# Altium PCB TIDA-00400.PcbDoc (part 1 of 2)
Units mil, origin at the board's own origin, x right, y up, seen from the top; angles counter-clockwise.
Board outline 2000 x 2000 mil, 2 copper layers (Top Layer, Bottom Layer), stack 62 mil thick; 123 components, 39 nets, 250 pads, 73 vias.
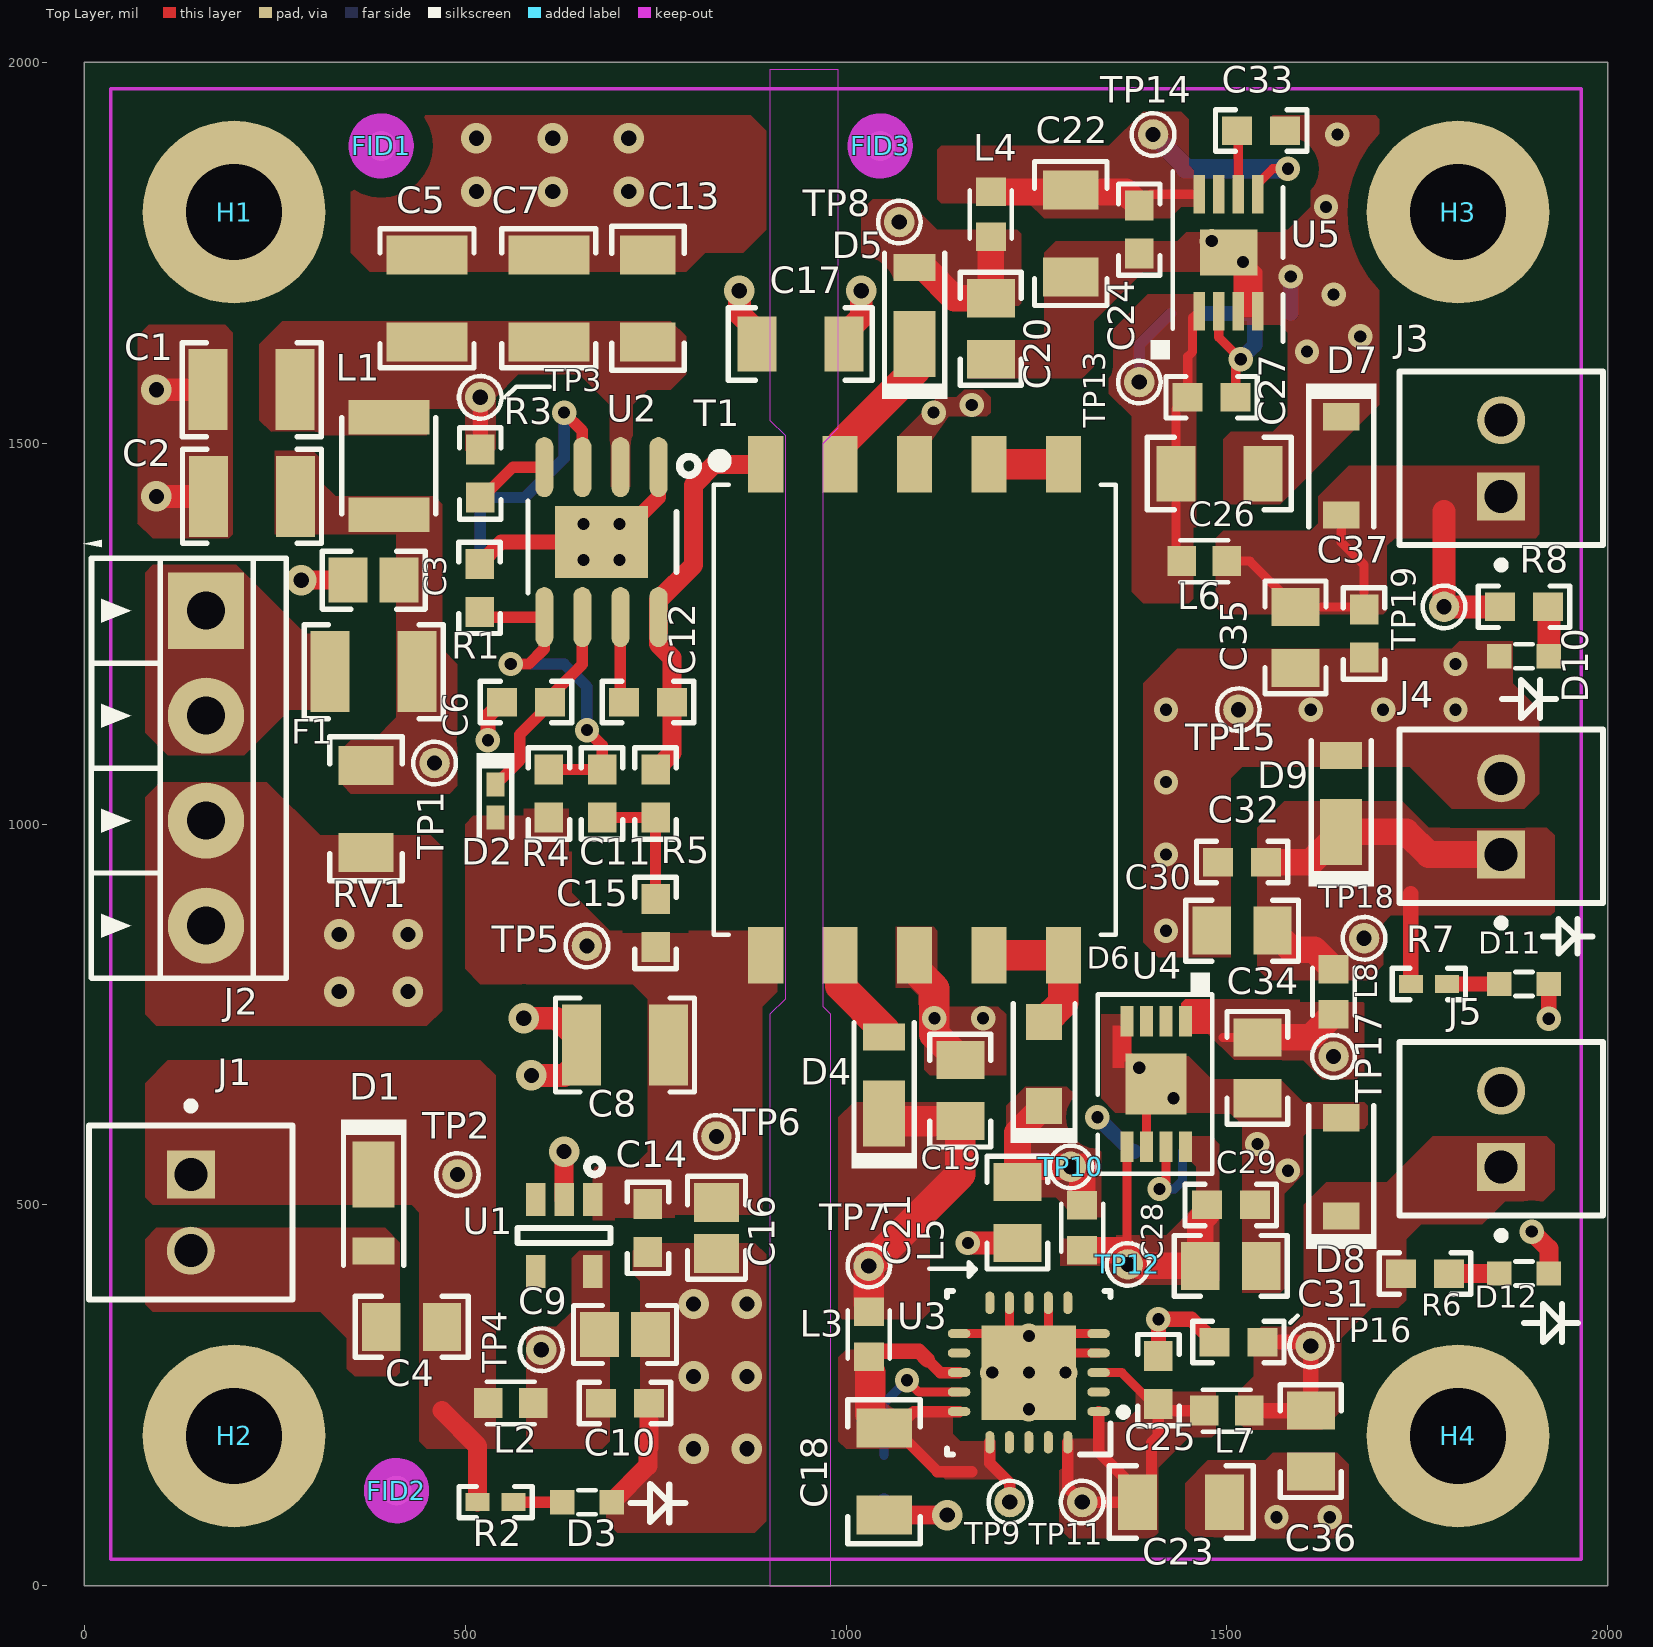
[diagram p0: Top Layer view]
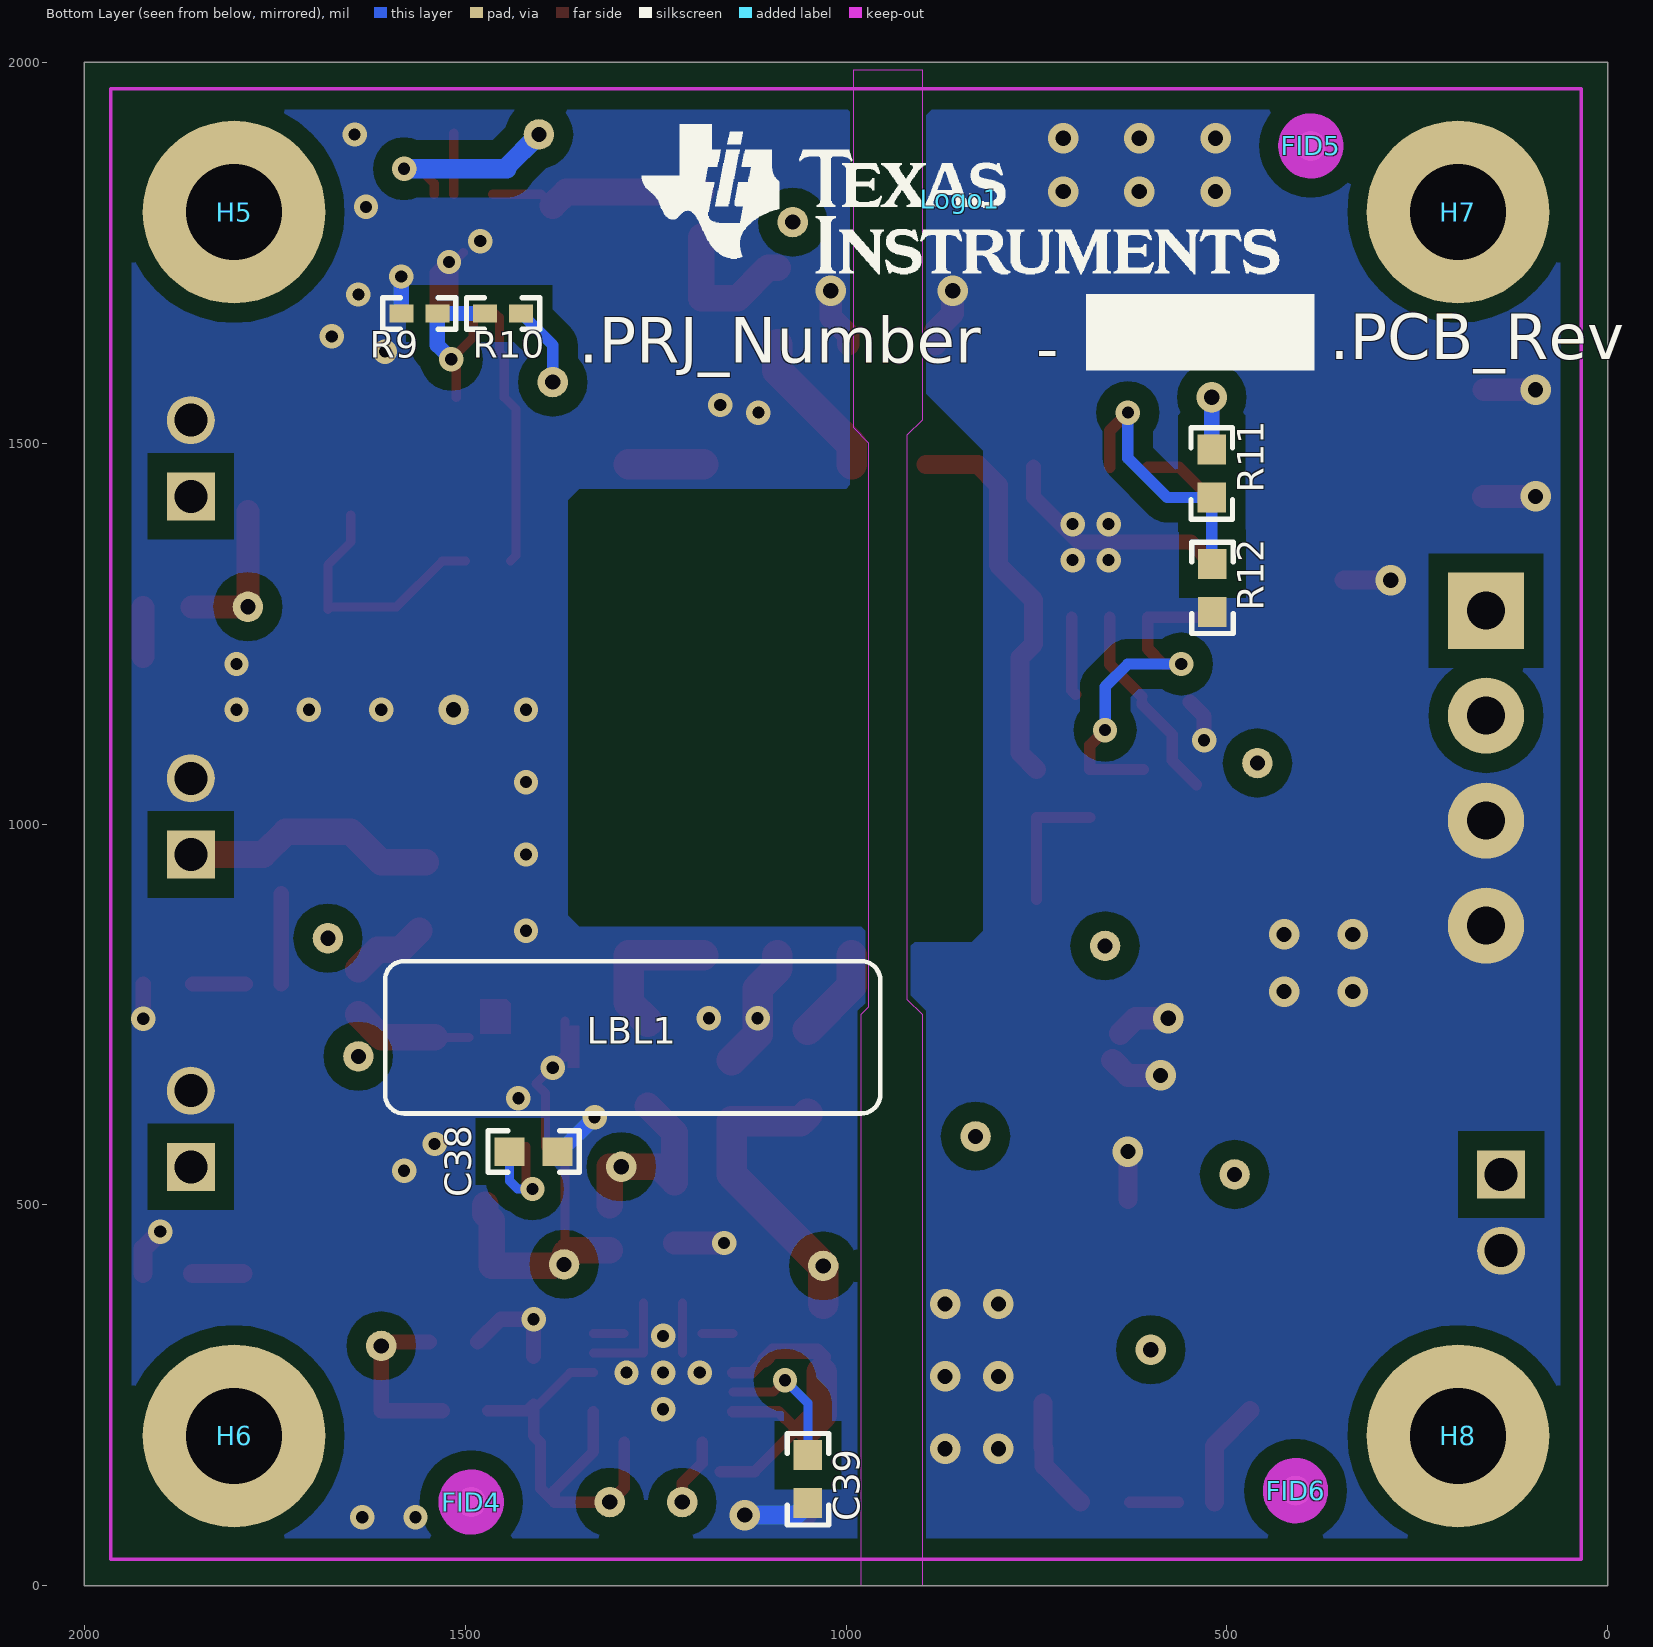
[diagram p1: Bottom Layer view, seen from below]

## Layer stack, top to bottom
Top Layer: signal copper 1.4
Dielectric: core 59.2, FR-4, Dk 4.8
Bottom Layer: signal copper 1.4

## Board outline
0,0 0,2000 2000,2000 2000,0

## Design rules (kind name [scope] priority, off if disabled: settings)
AcuteAngle [All] p1: minimum=4.50000000000000E+0001 checktracksonly=FALSE
AssemblyTestPointUsage [All] p1: valid=2
Clearance "Pad to Pad" [(InPadClass('Pad Class')) vs (InPadClass('Pad Class'))] p1: gap=8.6
Clearance "via 2 SMD Pin" [IsSMTPin vs IsVia] p2: gap=12
Clearance "Via 2 Via" [IsVia vs IsVia] p3: gap=10
Clearance Clearance_BoardEdge_MountingHoles [OnCopper and InComponentClass('Mounting Holes') vs IsKeepOut] p4: gap=40
Clearance Clearance_BoardEdge_Poly [OnCopper and InPoly vs IsKeepOut] p5: gap=25
Clearance Clearance_Poly [InPolygon] p6: gap=25
Clearance [All] p7: gap=11
ComponentClearance ComponentClearance_Shunt [InComponentClass('Header') vs InComponentClass('Shunt')] p1: gap=0 collisioncheckmode=3 verticalgap=0 showdistances=FALSE
ComponentClearance ComponentClearance_Logo [InComponentClass('Logo')] p2: gap=50 collisioncheckmode=3 verticalgap=10 showdistances=FALSE
ComponentClearance ComponentClearance_ScrewToNut [(HasFootprint('NY PMS 440 0025 PH')) vs (HasFootprint('Keystone_1902C'))] p3: gap=5 collisioncheckmode=3 verticalgap=10 showdistances=FALSE
ComponentClearance ComponentClearance_MountingHoles [InComponentClass('Mounting Holes')] p4: gap=250 collisioncheckmode=3 verticalgap=100000 showdistances=FALSE
ComponentClearance ComponentClearance_SmallPassives [HasFootprint('0201*') or HasFootprint('0402*') or HasFootprint('0508') or HasFootprint('0603*') or HasFootprint('0612') or HasFootprint('0805*') or HasFootprint('0815*') or HasFootprint('0830*') or HasFootprint('1206*') or HasFootprint('1210*') or HasFootprint('1808*') or HasFootprint('1812*') or HasFootprint('1825*') or HasFootprint('2010*') or HasFootprint('2220*') or HasFootprint('2225*') or HasFootprint('2512*') or HasFootprint('2728*') or HasFootprint('3518*') vs HasFootprint('0201*') or HasFootprint('0402*') or HasFootprint('0508') or HasFootprint('0603*') or HasFootprint('0612') or HasFootprint('0805*') or HasFootprint('0815*') or HasFootprint('0830*') or HasFootprint('1206*') or HasFootprint('1210*') or HasFootprint('1808*') or HasFootprint('1812*') or HasFootprint('1825*') or HasFootprint('2010*') or HasFootprint('2220*') or HasFootprint('2225*') or HasFootprint('2512*') or HasFootprint('2728*') or HasFootprint('3518*')] p5: gap=20 collisioncheckmode=3 verticalgap=10 showdistances=FALSE
ComponentClearance ComponentClearance_THtoSMT [IsThruComponent vs IsSMTComponent] p6: gap=100 collisioncheckmode=3 verticalgap=30 showdistances=FALSE
ComponentClearance ComponentClearance_THtoTH [IsThruComponent vs IsThruComponent] p7: gap=118.11 collisioncheckmode=3 verticalgap=30 showdistances=FALSE
ComponentClearance [All] p8: gap=40 collisioncheckmode=3 verticalgap=10 showdistances=FALSE
DiffPairsRouting [All] p1: maxlimit=100 minlimit=10 mostfreqgap=10 maxuncoupledlength=1000
FabricationTestPointUsage TestPointUsage [All] p1: valid=2 allowmultiple=FALSE
FabricationTestpoint Testpoint [All] p1: side=3 testpointundercomponent=TRUE minsize=40 maxsize=100 preferedsize=60 minholesize=0 maxholesize=40 preferedholesize=32 testpointgrid=1 allowsidetop=TRUE allowsidebottom=TRUE usegrid=TRUE gridtolerance=0.01
FanoutControl Fanout_LCC [IsLCC] p1: bgadir=Out bgaviamode=Centered fanoutstyle=Auto fanoutdirection=Alternating viagrid=1 // Fanout_LCC (Default Rule)
FanoutControl Fanout_BGA [IsBGA] p2: bgadir=Out bgaviamode=Centered fanoutstyle=Auto fanoutdirection=Alternating viagrid=1 // Fanout_BGA (Default Rule)
FanoutControl Fanout_Default [All] p4: bgadir=Out bgaviamode=Centered fanoutstyle=Auto fanoutdirection=Alternating viagrid=1 // Fanout_Default (Default Rule)
FanoutControl Fanout_Small [(CompPinCount < 5)] p5: bgadir=Out bgaviamode=Centered fanoutstyle=Auto fanoutdirection=OutThenIn viagrid=1 // Fanout_Small (Default Rule)
HoleSize [All] p1: absolutevalues=TRUE maxlimit=251 minlimit=8 maxpercent=80.000 minpercent=20.000
MinimumAnnularRing [All] p1: minimumring=8
MinimumSolderMaskSliver MinimumSolderMaskSliver_Logo [InComponentClass('Logo') vs InComponentClass('Logo')] p1: minsoldermaskwidth=0.7
MinimumSolderMaskSliver [All] p2: minsoldermaskwidth=3.94
PlaneConnect [All] p1: planeconnectstyle=Relief reliefexpansion=10 reliefentries=4 reliefconductorwidth=10 reliefairgap=10
PolygonConnect [All] p1: connectstyle=Direct reliefconductorwidth=10 reliefentries=4 polygonreliefangle="90 Angle" airgapwidth=10
RoutingVias ThermalPadVias [IsVia and InAnyComponent] p1: holewidth=20 width=40 viastyle="Through Hole" minholewidth=16 minwidth=32 maxholewidth=16 maxwidth=32
RoutingVias [All] p2: holewidth=20 width=40 viastyle="Through Hole" minholewidth=16 minwidth=32 maxholewidth=20 maxwidth=40
SMDToCorner [All] p1: distance=80000
SilkToSilkClearance [All] p1: silktosilkclearance=5
SilkscreenOverComponentPads [All] p1: minsilkscreentomaskgap=5
SolderMaskExpansion [All] p1: expansion=2.5
Width [All] p1: maxlimit=100 minlimit=11 preferedwidth=15 checkconnectedcopper=TRUE
14 further rules are at their usual default settings.

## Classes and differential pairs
pad class "Pad Class": D2-1 D2-2 U1-1 U1-2 U1-3 U1-4 U1-5 U2-1 U2-2 U2-3 U2-4 U2-5 U2-6 U2-7 U2-8 U2-9 U3-1 U3-2 U3-3 U3-4 U3-5 U3-6 U3-7 U3-8 U3-9 U3-10 U3-11 U3-12 U3-13 U3-14 U3-15 U3-16 U3-17 U3-18 U3-19 U3-20 U3-21 U4-1 U4-2 U4-3 U4-4 U4-5 U4-6 U4-7 U4-8 U4-9 U5-1 U5-2 U5-3 U5-4 U5-5 U5-6 U5-7 U5-8 U5-9
component class "Post Regulated LDO": C18 C22 C23 C24 C25 C26 C27 C28 C29 C30 C31 C32 C33 C34 C35 C36 C37 C38 C39 D7 D8 D9 D10 D11 D12 J3 J4 J5 L6 L7 L8 R6 R7 R8 R9 R10 TP11 TP13 TP16 TP17 TP18 TP19 U3 U4 U5
component class Isolated_Flybuck_PS: C1 C2 C3 C4 C5 C6 C7 C8 C9 C10 C11 C12 C13 C14 C15 C16 C17 C19 C20 C21 D1 D2 D3 D4 D5 D6 F1 J1 J2 L1 L2 L3 L4 L5 R1 R2 R3 R4 R5 R11 R12 RV1 T1 TP1 TP2 TP3 TP4 TP5 TP6 TP7 TP8 TP9 TP10 TP12 TP14 TP15 U1 U2
component class "Mounting Holes": H1 H2 H3 H4
component class Logo: Logo1
component class Hardware_ANSI-B: FID1 FID2 FID3 FID4 FID5 FID6 H1 H2 H3 H4 H5 H6 H7 H8 LBL1 Logo1 ZZ1 ZZ2 ZZ3 ZZ4
component class FiducialMark: FID1 FID2 FID3 FID4 FID5 FID6
component class AssemblyNote: ZZ1 ZZ2 ZZ3 ZZ4
component class Label: LBL1

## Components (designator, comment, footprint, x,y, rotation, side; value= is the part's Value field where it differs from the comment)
C1 "GRM32ER71H106KA12L" 1210 220,1570 r180 top (schematic designator C8)
C2 "GRM32ER71H106KA12L" 1210 220.31,1430 r180 top (schematic designator C6)
C3 "C0805C104K1RACTU" 0805 380,1320 r180 top (schematic designator C5)
C4 "C2012X5R1H475K125AB" 0805_HV 430,340 r0 top (schematic designator C16)
C5 "GRM32ER72A225KA35L" 1210 450,1690 r270 top (schematic designator C3)
C6 "GRM188R61H105KAALD" 0603 580,1160 r180 top (schematic designator C14)
C7 "GRM32ER72A225KA35L" 1210 610,1690 r270 top (schematic designator C1)
C8 "GMK325AB7106MM-T" 1210 710,710 r180 top (schematic designator C15)
C9 "0805YD106MAT2A" 0805 710,330 r0 top (schematic designator C19)
C10 "C0603C104K5RACTU" 0603 710,240 r0 top (schematic designator C20)
C11 "GRM188R72A104KA35D" 0603 680,1040 r90 top (schematic designator C10)
C12 "06031C103JAT2A" 0603 740,1160 r0 top (schematic designator C9)
C13 "GRM31MR72A474KA35L" 1206 740,1690 r270 top (schematic designator C4)
C14 "C0603C104K5RACTU" 0603 740,470 r270 top (schematic designator C18)
C15 "06031C332JAT2A" 0603 750,870 r270 top (schematic designator C12)
C16 "08055C105KAT2A" 0805 830,470 r270 top (schematic designator C17)
C17 "202R18W102KV4E" 1206 940,1630 r0 top (schematic designator C2)
C18 "GRM31CR71H475KA12L" 1206 1050,150 r270 top (schematic designator C24)
C19 "GRM21BR71E225KA73L" 0805_HV 1150,650 r90 top (schematic designator C7)
C20 "GRM21BR71E225KA73L" 0805_HV 1190,1650 r90 top (schematic designator C13)
C21 "GRM21BR71E225KA73L" 0805_HV 1225,490 r270 top (schematic designator C11)
C22 "GRM31CR71H475KA12L" 1206 1295,1775 r270 top (schematic designator C32)
C23 "GRM31CR71E106KA12L" 1206 1440,110 r0 top (schematic designator C27)
C24 "06035C104KAT2A" 0603 1385,1780 r90 top (schematic designator C31)
C25 "06035C104KAT2A" 0603 1410,270 r270 top (schematic designator C26)
C26 "GRM31CR71E106KA12L" 1206 1490,1460 r0 top (schematic designator C33)
C27 "06031C103JAT2A" 0603 1480,1560 r0 top (schematic designator C28)
C28 "GRM21BR61C226ME44" 0805_HV 1505,420 r0 top (schematic designator C39)
C29 "06035C104KAT2A" 0603 1505,500 r180 top (schematic designator C36)
C30 "C2012X5R1H475K125AB" 0805_HV 1520,860 r180 top (schematic designator C35)
C31 "06035C104KAT2A" 0603 1515,320 r0 top (schematic designator C23)
C32 "06035C104KAT2A" 0603 1520,950 r0 top (schematic designator C38)
C33 "06031C103JAT2A" 0603 1545,1910 r0 top (schematic designator C34)
C34 "GRM21BR61C226ME44" 0805_HV 1540,680 r270 top (schematic designator C40)
C35 "C2012X5R1H475K125AB" 0805_HV 1590,1245 r90 top (schematic designator C29)
C36 "C2012X5R1H475K125AB" 0805_HV 1610,190 r270 top (schematic designator C22)
C37 "06035C104KAT2A" 0603 1680,1250 r90 top (schematic designator C30)
C38 "06031C102JAT2A" 0603 1410,570 r180 bottom (schematic designator C37)
C39 "C1608X7R1E105K080AB" 0603 1050,140 r270 bottom (schematic designator C25)
D1 "PTZTE255.6B" powerDI123 380,490 r270 top (schematic designator D5)
D2 "SDM10U45-7-F" SOD-523 540,1030 r270 top (schematic designator D3)
D3 "LED_LG L29K-G2J1-24-Z" LED0603AA 660,110 r180 top (schematic designator D6)
D4 "DFLS1200-7" powerDI123 1050,670 r90 top (schematic designator D1)
D5 "DFLS1200-7" powerDI123 1090,1680 r90 top (schematic designator D4)
D6 "PMEG6010CEH,115" SOD-123F 1260,685 r90 top (schematic designator D2)
D7 "DZ2W18000L" SOD-123 1650,1470 r270 top (schematic designator D9)
D8 "DZ2W18000L" SOD-123 1650,550 r90 top (schematic designator D7)
D9 "PTZTE255.6B" powerDI123 1650,1040 r90 top (schematic designator D11)
D10 "LED_LG L29K-G2J1-24-Z" LED0603AA 1890,1220 r180 top
D11 "LED_LG L29K-G2J1-24-Z" LED0603AA 1890,790 r180 top (schematic designator D12)
D12 "LED_LG L29K-G2J1-24-Z" LED0603AA 1890,410 r180 top (schematic designator D8)
F1 "0ZCB0020FF2E" 1210 380,1200 r180 top
FID1 "Fiducial" Fiducial10-20 390,1890 r0 top
FID2 "Fiducial" Fiducial10-20 410,125 r0 top (schematic designator FID3)
FID3 "Fiducial" Fiducial10-20 1045,1890 r0 top (schematic designator FID2)
FID4 "Fiducial" Fiducial10-20 1492,110 r90 bottom (schematic designator FID6)
FID5 "Fiducial" Fiducial10-20 390,1890 r90 bottom
FID6 "Fiducial" Fiducial10-20 410,125 r90 bottom (schematic designator FID4)
H1 "NY PMS 440 0025 PH" "NY PMS 440 0025 PH" 196.85,1803.15 r0 top locked
H2 "NY PMS 440 0025 PH" "NY PMS 440 0025 PH" 196.85,196.85 r0 top locked (schematic designator H3)
H3 "NY PMS 440 0025 PH" "NY PMS 440 0025 PH" 1803.15,1803.15 r0 top locked (schematic designator H2)
H4 "NY PMS 440 0025 PH" "NY PMS 440 0025 PH" 1803.15,196.85 r0 top locked
H5 "1902C" Keystone_1902C 1803.15,1803.15 r180 bottom locked (schematic designator H6)
H6 "1902C" Keystone_1902C 1803.15,196.85 r180 bottom locked (schematic designator H8)
H7 "1902C" Keystone_1902C 196.85,1803.15 r180 bottom locked (schematic designator H5)
H8 "1902C" Keystone_1902C 196.85,196.85 r180 bottom locked (schematic designator H7)
J1 "282834-2" TEC_282834-2 140,490 r270 top (schematic designator J2)
J2 "ED555/4DS" TERM_BLK_ED555-4DS 160,1280 r270 top (schematic designator J1)
J3 "282834-2" TEC_282834-2 1860,1480 r90 top (schematic designator J4)
J4 "282834-2" TEC_282834-2 1860,1010 r90 top (schematic designator J5)
J5 "282834-2" TEC_282834-2 1860,600 r90 top (schematic designator J3)
L1 "3.3µH" IND_B82422H 400,1470 r90 top
L2 "1000 OHM" FB0603 560,240 r180 top (schematic designator L5)
L3 "1000 OHM" FB0603 1030,330 r270 top (schematic designator L2)
L4 "1000 OHM" FB0603 1190,1800 r90 top
L5 "1000 OHM" FB0603 1310,470 r270 top (schematic designator L3)
L6 "1000 OHM" FB0603 1470,1345 r0 top (schematic designator L7)
L7 "1000 OHM" FB0603 1500,230 r0 top (schematic designator L6)
L8 "1000 OHM" FB0603 1640,780 r90 top
LBL1 "Size: 0.65\" x 0.20 \"" Label_650x200 1280,720 r180 bottom
Logo1 "Texas Instruments" TI_Stacked_SolderMask_Small 850,1820 r180 bottom
R1 "RC0603FR-0727KL" 0603 518.98,1310 r270 top (schematic designator R6)
R2 "CRCW04021K20JNED" 0402 540,110 r0 top (schematic designator R7)
R3 "RC0603FR-0791KL" 0603 520,1460 r90 top (schematic designator R2)
R4 "RT0603BRD07189KL" 0603 610,1040 r270 top
R5 "RT0603BRD0756K2L" 0603 750,1040 r90 top (schematic designator R1)
R6 "CRCW06034K70JNEA" 0603 1760,410 r0 top (schematic designator R8)
R7 "CRCW04021K20JNED" 0402 1765,790 r0 top (schematic designator R12)
R8 "CRCW06034K70JNEA" 0603 1890,1285 r0 top (schematic designator R9)
R9 "TNPW04029K42BEED" 0402 1560,1670 r0 bottom (schematic designator R11)
R10 "CRCW0402110KFKED" 0402 1450,1670 r0 bottom
R11 "RT0603BRD0760K4L" 0603 520,1460 r90 bottom (schematic designator R3)
R12 "RC0603FR-074K87L" 0603 518.98,1310 r90 bottom (schematic designator R5)
RV1 "VC080530A650DP" 1206 370,1020 r90 top
T1 "750342178" WURTH_750313995 1090,1150 r0 top
TP1 "TP1_PD40_D0.5_S50" TP1_PD40_D0.5_S50 460,1080 r90 top (schematic designator TP2)
TP2 "TP1_PD40_D0.5_S50" TP1_PD40_D0.5_S50 490,540 r90 top (schematic designator TP11)
TP3 "TP1_PD40_D0.5_S50" TP1_PD40_D0.5_S50 520,1560 r90 top (schematic designator TP1)
TP4 "TP1_PD40_D0.5_S50" TP1_PD40_D0.5_S50 600,310 r90 top (schematic designator TP13)
TP5 "TP1_PD40_D0.5_S50" TP1_PD40_D0.5_S50 660,840 r90 top (schematic designator TP12)
TP6 "TP1_PD40_D0.5_S50" TP1_PD40_D0.5_S50 830,590 r90 top (schematic designator TP9)
TP7 "TP1_PD40_D0.5_S50" TP1_PD40_D0.5_S50 1030,420 r90 top (schematic designator TP3)
TP8 "TP1_PD40_D0.5_S50" TP1_PD40_D0.5_S50 1070,1790 r90 top
TP9 "TP1_PD40_D0.5_S50" TP1_PD40_D0.5_S50 1215,110 r90 top (schematic designator TP4)
TP10 "TP1_PD40_D0.5_S50" TP1_PD40_D0.5_S50 1295,550 r90 top (schematic designator TP5)
TP11 "TP1_PD40_D0.5_S50" TP1_PD40_D0.5_S50 1310,110 r90 top (schematic designator TP15)
TP12 "TP1_PD40_D0.5_S50" TP1_PD40_D0.5_S50 1370,422 r90 top (schematic designator TP6)
TP13 "TP1_PD40_D0.5_S50" TP1_PD40_D0.5_S50 1385,1580 r90 top (schematic designator TP17)
TP14 "TP1_PD40_D0.5_S50" TP1_PD40_D0.5_S50 1403,1905 r90 top (schematic designator TP10)
TP15 "TP1_PD40_D0.5_S50" TP1_PD40_D0.5_S50 1515,1150 r90 top (schematic designator TP7)
TP16 "TP-038" TP1_PD40_D0.5_S50 1610,315 r90 top (schematic designator TP14)
TP17 "TP1_PD40_D0.5_S50" TP1_PD40_D0.5_S50 1640,695 r90 top (schematic designator TP18)
TP18 "TP-038" TP1_PD40_D0.5_S50 1680,850 r90 top (schematic designator TP19)
TP19 "TP-038" TP1_PD40_D0.5_S50 1785,1285 r90 top (schematic designator TP16)
U1 "TPS70933DBVT" DBV0005A_N 630,460 r270 top (schematic designator U2)
U2 "LM5017MRE/NOPB" DDA0008B_N 678.98,1370 r270 top (schematic designator U1)
U3 "TPS7A4700RGW" RGW0020A 1240,280 r180 top
U4 "TPS7A1650DGNR" DGN_8P 1405.6,659.2 r270 top (schematic designator U5)
U5 "TPS7A3001DGNR" MSOP8(DGN) 1501.6,1750 r90 top (schematic designator U4)
ZZ1 "This Assembly Note is for PCB labels only" AssemblyNoteLabel -340,2673 r0 top
ZZ2 "These assemblies are ESD sensitive, ESD precautions shall be observed." AssemblyNote -340,2564.11 r0 top
ZZ3 "These assemblies must be clean and free from flux and all contaminants. Use of no clean flux is not acceptable." AssemblyNote -340,2475.56 r0 top
ZZ4 "These assemblies must comply with workmanship standards IPC-A-610 Class 2, unless otherwise specified." AssemblyNote -340,2387 r0 top

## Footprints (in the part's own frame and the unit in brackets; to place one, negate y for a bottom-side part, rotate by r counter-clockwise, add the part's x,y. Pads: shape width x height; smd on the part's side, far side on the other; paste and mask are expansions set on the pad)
0402 [mm] "0402 from SM-752 data"
  rect 0.8x0.6 smd: 1(-0.6,0) 2(0.6,0)
  silkscreen extent -1.22,-0.52 1.22,0.52, body extent -0.55,-0.3 0.55,0.3, height 0.6
0603 [mm] "0603 from SM-752 data"
  rect 1x0.95 smd: 1(-0.8,0) 2(0.8,0)
  silkscreen extent -1.52,-0.69 1.52,0.69, body extent -0.87,-0.47 0.87,0.47, height 0.85
0805 [mm] "0805 from SM-752 data"
  rect 1.3x1.5 smd: 1(-0.85,0) 2(0.85,0)
  silkscreen extent -1.72,-0.97 1.72,0.97, body extent -1.1,-0.72 1.1,0.72, height 1.1
0805_HV [mil] "0805 with 30mil clearance between pads"
  rect 50x63 smd: 1(-40,0) 2(40,0)
  silkscreen extent -74,-40 74,40, body extent -43,-29 43,29, height 43
1206 [mm] "1206 from SM-752 data"
  rect 1.3x1.85 smd: 1(-1.45,0) 2(1.45,0)
  silkscreen extent -2.4,-1.21 2.4,1.21, body extent -1.7,-0.9 1.7,0.9, height 1.35
1210 [mm] "1210 from SM-752 data"
  rect 1.3x2.7 smd: 1(-1.45,0) 2(1.45,0)
  silkscreen extent -2.32,-1.57 2.32,1.57, body extent -1.7,-1.35 1.7,1.35, height 1.35
AssemblyNote [mil] "Assembly Note"
AssemblyNoteLabel [mil] "Assembly Note for PCB Labels"
DBV0005A_N [mm] "SOT23, 5-Leads, Body 2.9x1.6mm, Pitch 0.95mm, Lead Span 2.8mm, IPC Medium Density"
  rect 1.1x0.65 smd: 1(-1.2,0.95) 2(-1.2,0) 3(-1.2,-0.95) 4(1.2,-0.95) 5(1.2,0.95)
  silkscreen extent -0.25,-1.55 0.25,1.55, body extent -1.42,-1.46 1.42,1.46, height 1.08
DDA0008B_N [mm] "SOIC, 8-Leads, Body 4.9x3.9mm, Pitch 1.27mm, Exposed Pad, IPC Medium Density"
  oval 2x0.6 smd: 1(-2.5,1.905) 2(-2.5,0.635) 3(-2.5,-0.635) 4(-2.5,-1.905) 5(2.5,-1.905) 6(2.5,-0.635) 7(2.5,0.635) 8(2.5,1.905)
  rect 2.41x3.1 smd: 9(0,0)
  silkscreen extent -1,2.5 1,2.5, body extent -2.98,-2.45 2.98,2.45, height 1.55
DGN_8P [mil]
  rect 40x17 smd: 1(-82.1,40) 2(-82.1,14.4) 3(-82.1,-11.2) 4(-82.1,-36.8) 5(82.9,-36.9) 6(82.9,-11.3) 7(82.9,14.3) 8(82.9,40)
  rect 80x80 smd: 9(0.2,1.4)
  silkscreen extent -146,47 -121,72
FB0603 [mm]
  rect 0.95x1 smd: 1(-0.75,0) 2(0.75,0)
  silkscreen extent -0.8,-0.7 0.8,0.7
Fiducial10-20 [mm]
  round 1 smd mask+0.5: 1(0,0)
  Top Layer keep-out circle w1.178: c0,0 r0.5
IND_B82422H [mm]
  rect 1.15x2.7 smd: 1(-1.625,0) 2(1.625,0)
  silkscreen extent -1.6,-1.57 1.6,1.57, body extent -1.6,-1.25 1.6,1.25, height 2.4
Keystone_1902C [mil] "Hex Standoff, 4-40 threaded, nylon"
  body extent -145,-126 146,126, height 501
Label_650x200 [mil] "Thermal Transfer Label"
  silkscreen extent -325,-100 325,100, body extent -326,-101 326,101, height 1
LED0603AA [mil]
  rect 32x32 smd: 1(-32.48,0) 2(32.48,0)
  silkscreen extent -129,-24 11,27
MSOP8(DGN) [mil]
  rect 50x15 smd: 1(-77,38) 2(-77,12.4) 3(-77,-13.2) 4(-77,-38.8) 5(76.6,-38.8) 6(76.6,-13.2) 7(76.6,12.4) 8(76.6,38)
  rect 60x75 smd: 9(0,-0.8)
  silkscreen extent -140,77 -115,102
"NY PMS 440 0025 PH" [mil] "4-40 nylon screw and mounting hole"
  round 240 hole 125.98: 1(0,0)
  body extent -130,-130 130,130, height 106
powerDI123 [mm] "Diodes Inc recommended land pattern, document number DS30628 Rev. 6-2"
  rect 2.2x1.4 smd: 1(-1.275,0)
  rect 0.9x1.4 smd: 2(1.275,0)
  silkscreen extent -3.1,-1.09 1.76,1.09, body extent -2.38,-0.97 1.52,0.96, height 1
RGW0020A [mm] "QFN, 20-Leads, Body 5x5mm, Pitch 0.65mm, Thermal Pad 3.15x3.15mm, TI Recommended"
  oval 0.75x0.3 smd: 1(-2.325,1.3) 2(-2.325,0.65) 3(-2.325,0) 4(-2.325,-0.65) 5(-2.325,-1.3) 11(2.325,-1.3) 12(2.325,-0.65) 13(2.325,0) 14(2.325,0.65) 15(2.325,1.3)
  oval 0.3x0.75 smd: 6(-1.3,-2.325) 7(-0.65,-2.325) 8(0,-2.325) 9(0.65,-2.325) 10(1.3,-2.325) 16(1.3,2.325) 17(0.65,2.325) 18(0,2.325) 19(-0.65,2.325) 20(-1.3,2.325)
  rect 3.15x3.15 smd paste-1.575: 21(0,0)
  silkscreen extent -2.73,-2.73 2.73,2.73, body extent -2.58,-2.57 2.57,2.58, height 1.01
SOD-123 [mm] "On Semi recommended land pattern"
  rect 0.915x1.22 smd: 1(-1.637,0) 2(1.637,0)
  silkscreen extent -2.74,-1.17 2.03,1.17, body extent -1.93,-0.9 1.93,0.9, height 1.35
SOD-123F [mm] "NXP recommended land pattern"
  rect 1.2x1.2 smd: 1(-1.4,0) 2(1.4,0)
  silkscreen extent -2.64,-1.12 2.01,1.12, body extent -1.8,-0.85 1.8,0.85, height 1.2
SOD-523 [mm] "NXP Semiconductor recommended land pattern, nominal STEP model"
  rect 0.8x0.6 smd: 1(-0.55,0) 2(0.55,0)
  silkscreen extent -1.6,-0.63 1.2,0.64, body extent -0.8,-0.4 0.8,0.4, height 0.72
TEC_282834-2 [mm] "TEC"
  rect 1.6x1.6 hole 1.1: 1(-1.27,0)
  round 1.6 hole 1.1: 2(1.27,0)
  silkscreen extent -3.66,-3.4 2.9,3.4, body extent -2.77,-3.25 2.77,3.25, height 10.01
TERM_BLK_ED555-4DS [mm]
  rect 2.54x2.54 hole 1.27: 1(0,0)
  round 2.54 hole 1.27: 2(3.5,0) 3(7,0) 4(10.5,0)
  silkscreen extent -2.36,-4.09 12.25,2.67, body extent -1.75,-3.8 12.25,2.7, height 8.2
TI_Stacked_SolderMask_Small [mil]
  silkscreen extent -418,-98 418,98
TP1_PD40_D0.5_S50 [mil]
  round 40 hole 20: 1(0,0)
  silkscreen extent -28,-28 28,28
WURTH_750313995 [mm] "WURTH"
  rect 1.17x1.88 smd: 1(-4.96,8.18) 2(-2.48,8.18) 3(0,8.18) 4(2.48,8.18) 5(4.96,8.18) 6(4.96,-8.18) 7(2.48,-8.18) 8(0,-8.18) 9(-2.48,-8.18) 10(-4.96,-8.18)
  silkscreen extent -6.7,-7.5 6.7,8.5, body extent -6.73,-8.9 6.73,8.9, height 12.7

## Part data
C1 C2: "CAP, CERM, 10uF, 50V, +/-10%, X7R, 1210"
C3: "CAP, CERM, 0.1uF, 100V, +/-10%, X7R, 0805"
C4 C30 C35 C36: "CAP, CERM, 4.7uF, 50V, +/-10%, X5R, 0805"
C5 C7: "CAP, CERM, 2.2uF, 100V, +/-10%, X7R, 1210"
C6: "CAP, CERM, 1uF, 50V, +/-10%, X5R, 0603"
C8: "CAP, CERM, 10uF, 35V, +/-20%, X7R, 1210"
C9: "CAP, CERM, 10uF, 16V, +/-20%, X5R, 0805"
C10 C14 C24 C25 C29 C31 C32 C37: "CAP, CERM, 0.1uF, 50V, +/-10%, X7R, 0603"
C11: "CAP, CERM, 0.1uF, 100V, +/-10%, X7R, 0603"
C12 C27 C33: "CAP, CERM, 0.01uF, 100V, +/-5%, X7R, 0603"
C13: "CAP, CERM, 0.47uF, 100V, +/-10%, X7R, 1206"
C15: "CAP, CERM, 3300pF, 100V, +/-5%, X7R, 0603"
C16: "CAP, CERM, 1uF, 50V, +/-10%, X7R, 0805"
C17: "CAP, CERM, 1000pF, 2KV 10% X7R 1206"
C18 C22: "CAP, CERM, 4.7uF, 50V, +/-10%, X7R, 1206"
C19 C20 C21: "CAP, CERM, 2.2uF, 25V, +/-10%, X7R, 0805"
C23 C26: "CAP, CERM, 10uF, 25V, +/-10%, X7R, 1206"
C28 C34: "CAP, CERM, 22uF, 16V, +/-20%, X5R, 0805"
C38: "CAP, CERM, 1000pF, 100V, +/-5%, X7R, 0603"
C39: "CAP, CERM, 1uF, 25V, +/-10%, X7R, 0603"
D1 D9: "DIODE ZENER 5.9V 1W PMDS"
D2: "Diode, Schottky, 45V, 0.1A, SOD-523"
D3 D10 D11 D12: "LED SmartLED Green 570NM"
D4 D5: "Diode, Schottky, 200V, 1A, PowerDI123"
D6: "Diode, Schottky, 60V, 1A, SOD-123F"
D7 D8: "Diode, Zener, 18V, 1W, SOD-123"
F1: library part 37215000001, "PTC RESTTBLE 0.05A 60V CHIP 1210"
FID1 FID2 FID3 FID4 FID5 FID6: "Fiducial mark.  There is nothing to buy or mount."
H1 H2 H3 H4: "Machine Screw, Round, #4-40 x 1/4, Nylon, Philips panhead"
H5 H6 H7 H8: "Standoff, Hex, 0.5\"L #4-40 Nylon"
J1 J3 J4 J5: "Terminal Block, 2x1, 2.54mm, TH"
J2: "Terminal Block, 6A, 3.5mm Pitch, 4-Pos, TH"
L1: library part IND_ELJEA_SERIES, "Inductor, Chip, ±10%"
L2 L3 L4 L5 L6 L7 L8: library part MMZ1608B102C, "FERRITE CHIP 1000 OHM 300MA 0603"
LBL1: library part THT-14-423-10, "Thermal Transfer Printable Labels, 0.650\" W x 0.200\" H - 10,000 per roll"
Logo1: library part TI_Logo, "Texas Instrument Corporate Signature"
R1: "RES, 27.0k ohm, 1%, 0.1W, 0603"
R2 R7: "RES, 1.2k ohm, 5%, 0.063W, 0402"
R3: "RES, 91.0k ohm, 1%, 0.1W, 0603"
R4: "RES, 189k ohm, 0.1%, 0.1W, 0603"
R5: "RES, 56.2k ohm, 0.1%, 0.1W, 0603"
R6 R8: "RES, 4.7k ohm, 5%, 0.1W, 0603"
R9: library part CRCW04029K31FKED, "RES, 9.42k ohm, 1%, 0.063W, 0402"
R10: "RES, 110k ohm, 1%, 0.063W, 0402"
R11: "RES, 60.4k ohm, 0.1%, 0.1W, 0603"
R12: "RES, 4.87k ohm, 1%, 0.1W, 0603"
RV1: library part VC120648D101DP, "VARISTOR 36.9V 30A 0805"
T1: library part 750313995, "Transformer, 50uH, SMT"
TP1 TP2 TP3 TP4 TP5 TP6 TP7 TP8 TP9 TP10 TP11 TP12 TP13 TP14 TP15 TP17: library part TP-040_RND, "Test Point 40mil pad 20mil drill"
TP16 TP18 TP19: "Test Point 40mil pad 20mil drill"
U1: "IC REG LDO 3.3V 0.15A SOT23-5"
U2: "100V, 600mA Constant On-Time Synchronous Buck Regulator, DDA0008B"
U3: "36-V, 1-A, 4.17-µVRMS, RF LDO Voltage Regulator, RGW0020A"
U4: library part TPS7A16XXDGN, "IC, 60-V, 6-A IQ, 100-mA, LDO Voltage Regulator with Enable and Power-Good Functions"
U5: "-36V, -200mA, Ultralow-Noise, Negative Linear Regulator"
ZZ1: library part AssemblyNoteLabel
ZZ2 ZZ3 ZZ4: library part AssemblyNote

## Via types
v1: diameter 32, hole 16, Top Layer to Bottom Layer, tented both sides, 48 vias
v2: diameter 40, hole 20, Top Layer to Bottom Layer, tented both sides, 25 vias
